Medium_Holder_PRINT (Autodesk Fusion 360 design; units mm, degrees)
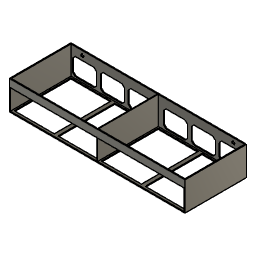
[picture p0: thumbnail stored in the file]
sketch "Bottom" plane through (0, 0, 0) normal (0, 0, 1) x axis (1, 0, 0)
  line L1 (232.6, 0) -> (0, 0)
  line L2 (232.6, 81.6) -> (232.6, 0)
  line L3 (0, 81.6) -> (232.6, 81.6)
  line L4 (0, 0) -> (0, 81.6)
  line L5 (231.4, 80.4) -> (1.2, 80.4)
  line L6 (231.4, 1.2) -> (231.4, 80.4)
  line L7 (1.2, 1.2) -> (231.4, 1.2)
  line L8 (1.2, 80.4) -> (1.2, 1.2)
  line L9 (3.2, 78.4) -> (3.2, 3.2)
  line L10 (34.2, 80.4) -> (33.4, 80.4)
  line L11 (33.4, 1.2) -> (34.2, 1.2)
  line L12 (67.2, 80.4) -> (66.4, 80.4)
  line L13 (66.4, 1.2) -> (67.2, 1.2)
  line L14 (100.2, 80.4) -> (99.4, 80.4)
  line L15 (99.4, 1.2032) -> (100.2, 1.2032)
  line L16 (133.2, 80.4) -> (132.4, 80.4)
  line L17 (132.4, 1.2) -> (133.2, 1.2)
  line L18 (166.2, 80.4) -> (165.4, 80.4)
  line L19 (165.4, 1.2) -> (166.2, 1.2)
  line L20 (199.2, 80.4) -> (198.4, 80.4)
  line L21 (198.4, 1.2) -> (199.2, 1.2)
  line L22 (229.4, 3.2) -> (229.4, 78.4)
  line L23 (232.2, 80.4) -> (231.4, 80.4)
  line L24 (231.4, 1.2) -> (232.2, 1.2)
  line L25 (115.9, 3.2) -> (115.9, 78.4)
  line L26 (116.7, 3.2) -> (116.7, 78.4)
  line L27 (116.7, 80.4) -> (116.7, 78.4)
  line L28 (115.9, 80.4) -> (115.9, 78.4)
  line L29 (116.7, 1.2) -> (116.7, 3.2)
  line L30 (115.9, 1.2) -> (115.9, 3.2)
  line L31 (113.9, 3.2) -> (113.9, 78.4)
  line L32 (113.9, 78.4) -> (3.2, 78.4)
  line L33 (3.2, 3.2) -> (113.9, 3.2)
  line L34 (118.7, 78.4) -> (229.4, 78.4)
  line L35 (118.7, 3.2) -> (118.7, 78.4)
  line L36 (118.7, 3.2) -> (229.4, 3.2)
  line L37 (56.2, 3.2) -> (56.2, 78.4)
  line L38 (61.2, 3.2) -> (61.2, 78.4)
  line L39 (171.7, 3.2) -> (171.7, 78.4)
  line L40 (176.7, 78.4) -> (176.7, 3.2)
  point P1 (0, 0)
  point P2 (0, 0)
  point P14 (34.2, 1.2)
  point P12 (33.4, 80.4)
  point P16 (66.4, 80.4)
  point P20 (99.4, 80.4)
  point P24 (132.4, 80.4)
  point P28 (165.4, 80.4)
  point P32 (198.4, 80.4)
  point P38 (231.4, 80.4)
  point P46 (116.7, 80.4)
  point P47 (115.9, 80.4)
  point P48 (116.7, 1.2)
  point P49 (115.9, 1.2)
  point P54 (56.2, 78.4)
  point P55 (56.2, 3.2)
  point P56 (61.2, 78.4)
  point P57 (61.2, 3.2)
  point P58 (171.7, 78.4)
  point P59 (171.7, 3.2)
  point P60 (176.7, 3.2)
  point P61 (176.7, 78.4)
  point P5 (0, 81.6)
  horizontal L1
  vertical L2
  horizontal L3
  vertical L4
  coincident P1 P2
  horizontal L5
  vertical L6
  horizontal L7
  vertical L8
  vertical L9
  horizontal L10
  coincident L7 P14
  coincident L5 P12
  horizontal L12
  horizontal L13
  coincident L5 P16
  horizontal L14
  horizontal L15
  coincident L5 P20
  horizontal L16
  horizontal L17
  coincident L5 P24
  horizontal L18
  horizontal L19
  coincident L5 P28
  horizontal L20
  horizontal L21
  coincident L5 P32
  vertical L22
  horizontal L23
  horizontal L24
  coincident L5 P38
  coincident L5 P46
  perpendicular L5 L27
  coincident L5 P47
  perpendicular L5 L28
  coincident L7 P48
  perpendicular L7 L29
  coincident L7 P49
  perpendicular L7 L30
  perpendicular L31 L32
  perpendicular L9 L33
  perpendicular L25 L34
  perpendicular L35 L36
  coincident L32 P54
  coincident L33 P55
  perpendicular L33 L37
  coincident L32 P56
  coincident L33 P57
  perpendicular L33 L38
  coincident L34 P58
  coincident L36 P59
  perpendicular L36 L39
  coincident L36 P60
  coincident L34 P61
  perpendicular L34 L40
  dimension "d1" distance L4 L8 = 1.2
  dimension "d2" distance L3 L5 = 1.2
  dimension "d3" distance L1 L7 = 1.2
  dimension "d4" distance L2 L6 = 1.2
  dimension "d5" distance L8 L9 = 2
  dimension "d8" distance P2 P5 = 81.6
  dimension "d52" distance L6 L22 = 2
  dimension "d173" distance L9 L25 = 112.7 (= "( ( 226.2 / 2 ) * 1 mm ) - 0.4 mm")
  dimension "d174" distance L22 L26 = 112.7 (= "( ( 226.2 / 2 ) * 1 mm ) - 0.4 mm")
  dimension "d175" distance L25 L26 = 0.8
  dimension "d190" distance L25 L31 = 2
  dimension "d191" distance L5 L32 = 2
  dimension "d192" distance L7 L33 = 2
  dimension "d193" distance L26 L35 = 2
  dimension "d194" distance L7 L36 = 2
  dimension "d195" distance L5 L34 = 2
  dimension "d203" distance L37 L38 = 5
  dimension "d204" distance L9 L37 = 53
  dimension "d206" distance L39 L40 = 5
  dimension "d207" distance L35 L39 = 53
extrude "Extrude2" new body sketch "Bottom" profile of L1 L2 L3 L4 L5 L6 L7 L8 L10 L11 L12 L13 L14 L16 L17 L18 L19 L20 L21 L25 L26 L27 L28 L29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 along normal blind 38.2
sketch "Front" plane through (0, 0, 0) normal (0, -1, 0) x axis (1, 0, 0)
  line L1 (232.6, 0) -> (0, 0)
  line L2 (232.6, 38.2) -> (232.6, 0)
  line L3 (0, 38.2) -> (232.6, 38.2)
  line L4 (0, 0) -> (0, 38.2)
  line L5 (33.4, 28.2) -> (1.2, 28.2)
  line L6 (1.2, 1.2) -> (33.4, 1.2)
  line L7 (1.2, 28.2) -> (1.2, 1.2)
  line L8 (1.2, 38.2) -> (1.2, 0)
  line L9 (231.4, 1.2) -> (231.4, 28.2)
  line L10 (231.4, 28.2) -> (33.4, 28.2)
  line L11 (33.4, 1.2) -> (231.4, 1.2)
  point P6 (1.2, 28.2)
  point P9 (1.2, 1.2)
  point P12 (231.4, 28.2)
  point P13 (231.4, 1.2)
  horizontal L5
  horizontal L6
  vertical L7
  collinear L7 L8
  vertical L9
  perpendicular L9 L10
  dimension "d80" distance P6 P9 = 27
  dimension "d83" distance L3 L5 = 10
  dimension "d91" distance P12 P13 = 27
  dimension "d294" distance L2 L9 = 1.2
sketch "Back" plane through (0, 80.4, 0) normal (0, -1, 0) x axis (1, 0, 0)
  line L1 (231.4, 38.2) -> (231.4, 0)
  line L2 (1.2, 38.2) -> (115.9, 38.2)
  line L3 (1.2, 0) -> (1.2, 38.2)
  line L4 (3.2, 7) -> (3.2, 23)
  line L5 (115.9, 38.2) -> (115.9, 0)
  line L6 (116.7, 0) -> (116.7, 38.2)
  line L7 (116.7, 38.2) -> (231.4, 38.2)
  line L8 (231.4, 0) -> (116.7, 0)
  line L9 (115.9, 0) -> (1.2, 0)
  line L10 (6.7355, 26.5355) -> (3.2, 23)
  line L11 (8.2, 23) -> (3.2, 23)
  line L12 (31.7355, 26.5355) -> (6.7355, 26.5355)
  line L13 (35.2711, 23) -> (31.7355, 26.5355)
  line L14 (36.7355, 26.5355) -> (31.7355, 26.5355)
  line L15 (35.2711, 7) -> (35.2711, 23)
  line L16 (31.7355, 3.4645) -> (35.2711, 7)
  line L17 (6.7355, 3.4645) -> (3.2, 7)
  line L18 (8.2, 7) -> (3.2, 7)
  line L19 (31.7355, 3.4645) -> (6.7355, 3.4645)
  line L20 (68.6066, 26.5355) -> (43.6066, 26.5355)
  line L21 (43.6066, 26.5355) -> (40.0711, 23)
  line L22 (40.0711, 7) -> (40.0711, 23)
  line L23 (43.6066, 3.4645) -> (40.0711, 7)
  line L24 (68.6066, 3.4645) -> (43.6066, 3.4645)
  line L25 (68.6066, 3.4645) -> (72.1421, 7)
  line L26 (72.1421, 7) -> (72.1421, 23)
  line L27 (72.1421, 23) -> (68.6066, 26.5355)
  line L28 (105.4777, 26.5355) -> (80.4777, 26.5355)
  line L29 (80.4777, 26.5355) -> (76.9421, 23)
  line L30 (76.9421, 7) -> (76.9421, 23)
  line L31 (80.4777, 3.4645) -> (76.9421, 7)
  line L32 (105.4777, 3.4645) -> (80.4777, 3.4645)
  line L33 (105.4777, 3.4645) -> (109.0132, 7)
  line L34 (109.0132, 7) -> (109.0132, 23)
  line L35 (109.0132, 23) -> (105.4777, 26.5355)
  line L36 (152.1223, 26.5355) -> (127.1223, 26.5355)
  line L37 (127.1223, 26.5355) -> (123.5868, 23)
  line L38 (123.5868, 7) -> (123.5868, 23)
  line L39 (127.1223, 3.4645) -> (123.5868, 7)
  line L40 (152.1223, 3.4645) -> (127.1223, 3.4645)
  line L41 (152.1223, 3.4645) -> (155.6579, 7)
  line L42 (155.6579, 7) -> (155.6579, 23)
  line L43 (155.6579, 23) -> (152.1223, 26.5355)
  line L44 (188.9934, 26.5355) -> (163.9934, 26.5355)
  line L45 (163.9934, 26.5355) -> (160.4579, 23)
  line L46 (160.4579, 7) -> (160.4579, 23)
  line L47 (163.9934, 3.4645) -> (160.4579, 7)
  line L48 (188.9934, 3.4645) -> (163.9934, 3.4645)
  line L49 (188.9934, 3.4645) -> (192.5289, 7)
  line L50 (192.5289, 7) -> (192.5289, 23)
  line L51 (192.5289, 23) -> (188.9934, 26.5355)
  line L52 (225.8645, 26.5355) -> (200.8645, 26.5355)
  line L53 (200.8645, 26.5355) -> (197.3289, 23)
  line L54 (197.3289, 7) -> (197.3289, 23)
  line L55 (200.8645, 3.4645) -> (197.3289, 7)
  line L56 (225.8645, 3.4645) -> (200.8645, 3.4645)
  line L57 (225.8645, 3.4645) -> (229.4, 7)
  line L58 (229.4, 7) -> (229.4, 23)
  line L59 (229.4, 23) -> (225.8645, 26.5355)
  line L60 (232.6, 38.2) -> (232.6, 0)
  point P5 (3.2, 7)
  point P6 (3.2, 23)
  point P12 (6.7355, 26.5355)
  point P14 (31.7355, 26.5355)
  point P15 (35.2711, 23)
  point P17 (35.2711, 7)
  point P18 (31.7355, 3.4645)
  point P19 (6.7355, 3.4645)
  point P23 (40.0711, 23)
  point P26 (40.0711, 7)
  point P21 (43.6066, 26.5355)
  point P28 (68.6066, 26.5355)
  point P27 (72.1421, 23)
  point P22 (68.6066, 3.4645)
  point P25 (72.1421, 7)
  point P24 (43.6066, 3.4645)
  point P31 (76.9421, 23)
  point P34 (76.9421, 7)
  point P29 (80.4777, 26.5355)
  point P36 (105.4777, 26.5355)
  point P35 (109.0132, 23)
  point P30 (105.4777, 3.4645)
  point P33 (109.0132, 7)
  point P32 (80.4777, 3.4645)
  point P39 (123.5868, 23)
  point P42 (123.5868, 7)
  point P37 (127.1223, 26.5355)
  point P44 (152.1223, 26.5355)
  point P43 (155.6579, 23)
  point P38 (152.1223, 3.4645)
  point P41 (155.6579, 7)
  point P40 (127.1223, 3.4645)
  point P47 (160.4579, 23)
  point P50 (160.4579, 7)
  point P45 (163.9934, 26.5355)
  point P52 (188.9934, 26.5355)
  point P51 (192.5289, 23)
  point P46 (188.9934, 3.4645)
  point P49 (192.5289, 7)
  point P48 (163.9934, 3.4645)
  point P55 (197.3289, 23)
  point P58 (197.3289, 7)
  point P53 (200.8645, 26.5355)
  point P60 (225.8645, 26.5355)
  point P59 (229.4, 23)
  point P54 (225.8645, 3.4645)
  point P57 (229.4, 7)
  point P56 (200.8645, 3.4645)
  parallel L3 L4
  horizontal L11
  horizontal L12
  horizontal L14
  vertical L15
  horizontal L18
  horizontal L20
  vertical L26
  horizontal L28
  vertical L34
  horizontal L36
  vertical L42
  horizontal L44
  vertical L50
  horizontal L52
  vertical L58
  dimension "d102" distance L3 L4 = 2
  dimension "d211" distance P5 P6 = 16
  dimension "d214" distance P5 L9 = 7
  dimension "d216" distance P6 P12 = 5
  dimension "d217" angle L10 L11 = 45
  dimension "d218" distance P12 P14 = 25
  dimension "d219" angle L13 L14 = 45
  dimension "d220" distance P14 P15 = 5
  dimension "d221" angle L15 L16 = 135
  dimension "d222" distance P17 P18 = 5
  dimension "d223" angle L17 L18 = 45
  dimension "d224" distance P5 P19 = 5
  dimension "d225" distance P23 P26 = 16
  dimension "d226" distance P21 P23 = 5
  dimension "d227" distance P21 P28 = 25
  dimension "d228" distance P27 P28 = 5
  dimension "d229" angle L25 L26 = 135
  dimension "d230" distance P22 P25 = 5
  dimension "d231" distance P24 P26 = 5
  dimension "d232" distance P31 P34 = 16
  dimension "d233" distance P29 P31 = 5
  dimension "d234" distance P29 P36 = 25
  dimension "d235" distance P35 P36 = 5
  dimension "d236" angle L33 L34 = 135
  dimension "d237" distance P30 P33 = 5
  dimension "d238" distance P32 P34 = 5
  dimension "d239" distance P39 P42 = 16
  dimension "d240" distance P37 P39 = 5
  dimension "d241" distance P37 P44 = 25
  dimension "d242" distance P43 P44 = 5
  dimension "d243" angle L41 L42 = 135
  dimension "d244" distance P38 P41 = 5
  dimension "d245" distance P40 P42 = 5
  dimension "d246" distance P47 P50 = 16
  dimension "d247" distance P45 P47 = 5
  dimension "d248" distance P45 P52 = 25
  dimension "d249" distance P51 P52 = 5
  dimension "d250" angle L49 L50 = 135
  dimension "d251" distance P46 P49 = 5
  dimension "d252" distance P48 P50 = 5
  dimension "d253" distance P55 P58 = 16
  dimension "d254" distance P53 P55 = 5
  dimension "d255" distance P53 P60 = 25
  dimension "d256" distance P59 P60 = 5
  dimension "d257" angle L57 L58 = 135
  dimension "d258" distance P54 P57 = 5
  dimension "d259" distance P56 P58 = 5
  dimension "d260" distance L15 L22 = 4.8
  dimension "d261" distance L26 L30 = 4.8
  dimension "d262" distance L50 L54 = 4.8
  dimension "d263" distance L42 L46 = 4.8
  dimension "d264" distance L36 L40 = 23.0711
  dimension "d265" distance L8 L40 = 3.4645
  dimension "d266" distance L38 L42 = 32.0711
  dimension "d267" distance L8 L48 = 3.4645
  dimension "d268" distance L58 L60 = 3.2
  dimension "d269" distance L6 L38 = 6.8868
  dimension "d270" angle L44 L45 = 135
  dimension "d272" angle L44 L51 = 135
  dimension "d273" distance L44 L48 = 23.0711
  dimension "d274" angle L52 L53 = 135
  dimension "d275" distance L52 L56 = 23.0711
  dimension "d279" angle L36 L37 = 135
  dimension "d280" distance L28 L32 = 23.0711
  dimension "d281" angle L28 L35 = 135
  dimension "d283" distance L30 L34 = 32.0711
  dimension "d284" distance L22 L26 = 32.0711
  dimension "d285" angle L20 L21 = 135
  dimension "d286" angle L20 L27 = 135
  dimension "d287" distance L20 L24 = 23.0711
  dimension "d288" angle L21 L22 = 135
  dimension "d290" distance L9 L24 = 3.4645
  dimension "d292" angle L16 L19 = 135
  dimension "d297" distance L9 L32 = 3.4645
  dimension "d298" distance L8 L56 = 3.4645
sketch "Mounting" plane through (0, 80.4, 0) normal (0, -1, 0) x axis (1, 0, 0)
  line L1 (231.4, 38.2) -> (231.4, 0)
  line L2 (1.2, 38.2) -> (115.9, 38.2)
  line L3 (1.2, 0) -> (1.2, 38.2)
  line L4 (115.9, 38.2) -> (115.9, 0)
  line L5 (116.7, 0) -> (116.7, 38.2)
  line L6 (116.7, 38.2) -> (231.4, 38.2)
  line L7 (231.4, 0) -> (116.7, 0)
  line L8 (115.9, 0) -> (1.2, 0)
  circle C1 centre (216.3, 32.2) radius 2
  circle C2 centre (16.3, 32.2) radius 2
  point P6 (16.3, 32.2)
  point P5 (216.3, 32.2)
  dimension "d165" diameter C1 = 4
  dimension "d166" diameter C2 = 4
  dimension "d167" distance L3 P6 = 15.1
  dimension "d168" distance L2 P6 = 6
  dimension "d169" distance L1 P5 = 15.1
  dimension "d170" distance L2 P5 = 6
extrude "Extrude9" cut sketch "Front" profile of L5 L6 L7 L8 L9 L10 L11 to an object
extrude "Extrude10" cut sketch "Back" profile of L4 L10 L12 L13 L15 L16 L17 L19 L20 L21 L22 L23 L24 L25 L26 L27 L28 L29 L30 L31 L32 L33 L34 L35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 against normal blind 1.2
extrude "Extrude11" cut sketch "Mounting" profile of C1 C2 against normal blind 1.2
extrude "Extrude12" add sketch "Bottom" profile of L5 L7 L8 L9 L10 L11 L12 L13 L14 L28 L30 to an object
extrude "Extrude13" add sketch "Bottom" profile of L5 L6 L7 L16 L17 L18 L19 L20 L21 L22 L26 L27 L29 L32 L33 L34 L35 L36 L37 L38 to an object
extrude "Extrude14" add of existing geometry to an object
extrude "Extrude15" add sketch "Bottom" profile of L34 L36 L39 L40 along normal blind 1.2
